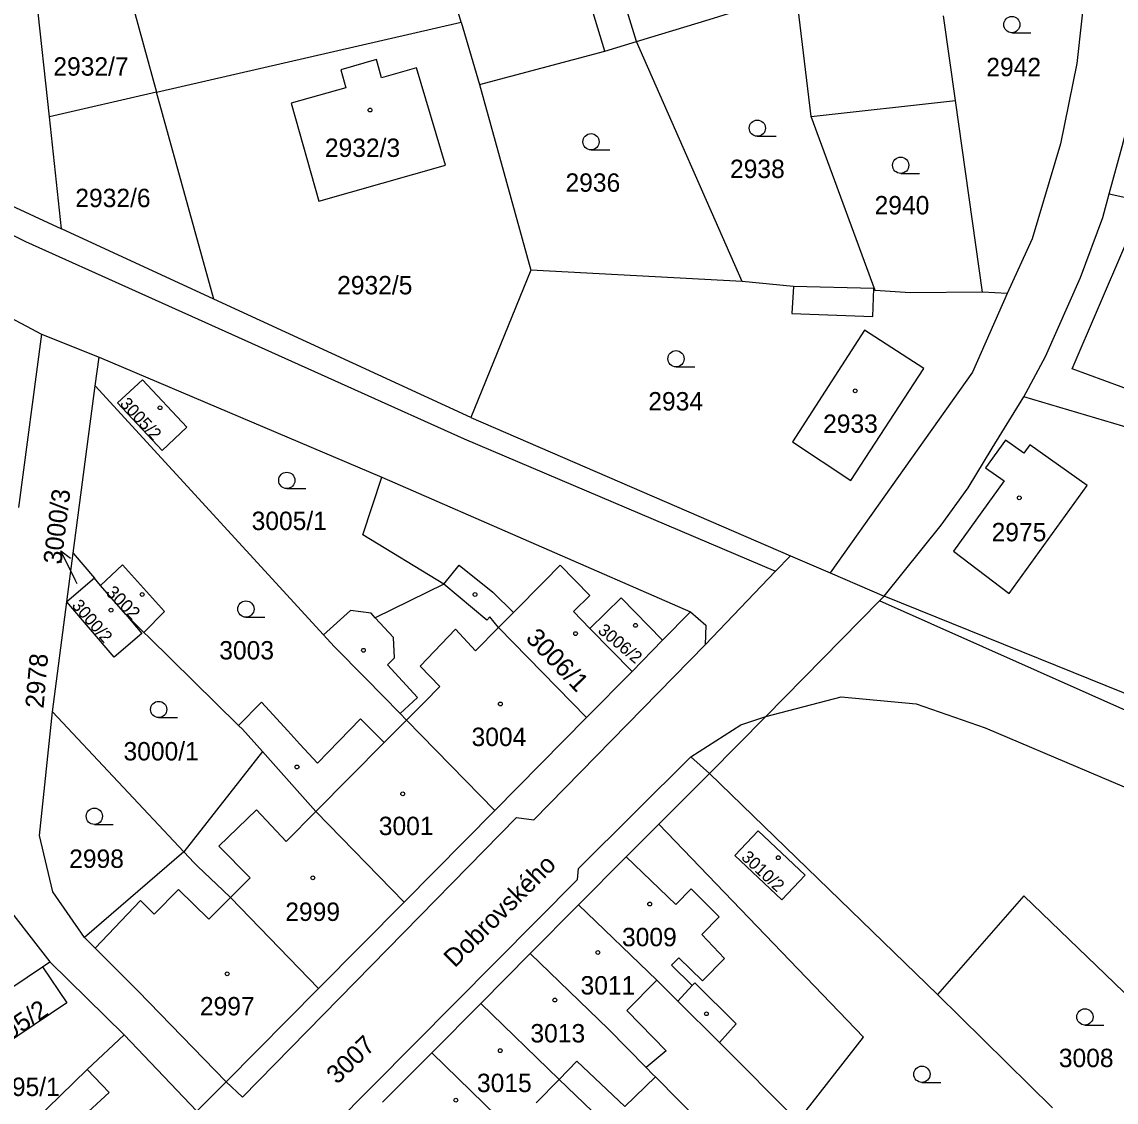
# Model space of a CAD drawing. Extents: x -527335 to -526256, y -1079142 to -1077836.
# Drawn here: x -526682.7 to -526581.6, y -1078714.2 to -1078614.4 of the extents above; entities that cross this region are included whole.
import ezdxf

# ---------------------------------------------------------------- set-up
doc = ezdxf.new("R2010")
doc.units = 0
for name, color, linetype in [('Hranice parcel', 7, 'Continuous'), ('Parcelní čísla', 7, 'Continuous'), ('Pop  PČ popisy', 7, 'Continuous'), ('Vnitřní kresba', 7, 'Continuous'), ('Značky budov', 7, 'Continuous'), ('Značky kultur', 7, 'Continuous')]:
    doc.layers.add(name, color=color, linetype=linetype)

msp = doc.modelspace()

# ---------------------------------------------------------------- linework, layer by layer
at = {"layer": 'Hranice parcel'}
for p, q in [((-526642.16, -1078614.41), (-526648.3, -1078593.48)), ((-526675.77, -1078601.05), (-526670.3, -1078620.85)), ((-526680.21, -1078623.13), (-526682.38, -1078602.87)), ((-526609.83, -1078623.11), (-526611.2, -1078611.62)), ((-526721.35, -1078614.01), (-526679.1, -1078633.49)), ((-526670.3, -1078620.85), (-526642.16, -1078614.41)), ((-526642.16, -1078614.41), (-526640.47, -1078620.16)), ((-526596.5, -1078621.62), (-526597.58, -1078613.8)), ((-526616.19, -1078638.37), (-526625.97, -1078616.19)), ((-526640.47, -1078620.16), (-526635.71, -1078637.32)), ((-526670.3, -1078620.85), (-526680.21, -1078623.13)), ((-526665.02, -1078639.98), (-526670.3, -1078620.85)), ((-526609.83, -1078623.11), (-526596.5, -1078621.62)), ((-526593.98, -1078639.34), (-526596.5, -1078621.62)), ((-526679.1, -1078633.49), (-526680.21, -1078623.13)), ((-526603.92, -1078639.18), (-526609.83, -1078623.11)), ((-526582.29, -1078630.26), (-526567.45, -1078633.62)), ((-526665.02, -1078639.98), (-526679.1, -1078633.49)), ((-526635.71, -1078637.32), (-526641.28, -1078650.93)), ((-526616.19, -1078638.37), (-526635.71, -1078637.32)), ((-526591.7, -1078639.47), (-526593.98, -1078639.34)), ((-526641.28, -1078650.93), (-526665.02, -1078639.98)), ((-526680.92, -1078643.22), (-526683.06, -1078659.24)), ((-526680.92, -1078643.22), (-526675.6, -1078645.35)), ((-526675.97, -1078647.99), (-526675.6, -1078645.35)), ((-526675.6, -1078645.35), (-526649.49, -1078656.45)), ((-526654.89, -1078671), (-526675.97, -1078647.99)), ((-526575.77, -1078653.31), (-526590.18, -1078649.02)), ((-526641.28, -1078650.93), (-526611.73, -1078663.7)), ((-526649.49, -1078656.45), (-526620.98, -1078668.88)), ((-526678.59, -1078667.96), (-526678, -1078663.47)), ((-526678, -1078663.47), (-526676.05, -1078665.78)), ((-526611.73, -1078663.7), (-526608.06, -1078665.29)), ((-526676.05, -1078665.78), (-526678.59, -1078667.96)), ((-526675.49, -1078666.45), (-526676.05, -1078665.78)), ((-526608.06, -1078665.29), (-526603.09, -1078667.44)), ((-526673.15, -1078669.14), (-526675.49, -1078666.45)), ((-526679.91, -1078678.13), (-526678.59, -1078667.96)), ((-526565.26, -1078682.7), (-526603.09, -1078667.44)), ((-526623.55, -1078671.51), (-526620.98, -1078668.88)), ((-526671.47, -1078670.79), (-526673.15, -1078669.14)), ((-526626.37, -1078674.41), (-526623.55, -1078671.51)), ((-526630.57, -1078678.66), (-526626.37, -1078674.41)), ((-526667.79, -1078691.06), (-526679.91, -1078678.13)), ((-526639.06, -1078687.24), (-526647.2, -1078678.89)), ((-526639.06, -1078687.24), (-526630.57, -1078678.66)), ((-526619.22, -1078683.84), (-526614.02, -1078678.55)), ((-526660.52, -1078681.79), (-526667.79, -1078691.06)), ((-526619.22, -1078683.84), (-526623.89, -1078688.51)), ((-526598.14, -1078704.26), (-526619.22, -1078683.84)), ((-526647.44, -1078695.71), (-526639.06, -1078687.24)), ((-526623.89, -1078688.51), (-526626.91, -1078691.53)), ((-526667.79, -1078691.06), (-526676.97, -1078698.98)), ((-526626.91, -1078691.53), (-526631.31, -1078695.96)), ((-526685.78, -1078694.02), (-526680.15, -1078701.23)), ((-526655.33, -1078703.7), (-526647.44, -1078695.71)), ((-526635.79, -1078700.47), (-526631.31, -1078695.96)), ((-526680.84, -1078701.69), (-526680.15, -1078701.23)), ((-526680.15, -1078701.23), (-526673.29, -1078707.97)), ((-526640.35, -1078705.07), (-526635.79, -1078700.47)), ((-526689.86, -1078707.76), (-526680.84, -1078701.69)), ((-526663.87, -1078712.33), (-526655.33, -1078703.7)), ((-526587.53, -1078714.71), (-526598.14, -1078704.26)), ((-526644.88, -1078709.64), (-526640.35, -1078705.07)), ((-526673.29, -1078707.97), (-526666.58, -1078715.02)), ((-526649.43, -1078714.21), (-526644.88, -1078709.64)), ((-526666.58, -1078715.02), (-526663.87, -1078712.33))]:
    msp.add_line(p, q, dxfattribs=at)
for points in [[(-526625.97, -1078616.19), (-526627.66, -1078610.64), (-526633.95, -1078589.47)], [(-526583.43, -1078599.56), (-526584.01, -1078606.72), (-526585.28, -1078618.21), (-526586.79, -1078625.64), (-526589.4, -1078634.43), (-526591.7, -1078639.47)], [(-526582.29, -1078630.26), (-526581.08, -1078625.88), (-526580.12, -1078622.23), (-526579.3, -1078618.4), (-526578.59, -1078614.59), (-526578.22, -1078610.5)], [(-526625.97, -1078616.19), (-526619.24, -1078614.14), (-526611.2, -1078611.62)], [(-526640.47, -1078620.16), (-526628.89, -1078617.08), (-526625.97, -1078616.19)], [(-526646.3, -1078618.62), (-526649.52, -1078619.53), (-526649.99, -1078617.86), (-526653.29, -1078618.79), (-526652.82, -1078620.46), (-526657.87, -1078621.89), (-526655.31, -1078630.94), (-526643.61, -1078627.6), (-526646.3, -1078618.62)], [(-526590.18, -1078649.02), (-526588.18, -1078645.3), (-526584.94, -1078638), (-526582.87, -1078632.45), (-526582.29, -1078630.26)], [(-526697.66, -1078634.2), (-526691.45, -1078637.64), (-526680.92, -1078643.22)], [(-526603.92, -1078639.18), (-526604.04, -1078639.02), (-526611.44, -1078638.83), (-526616.19, -1078638.37)], [(-526591.7, -1078639.47), (-526594.93, -1078646.75), (-526608.06, -1078665.29)], [(-526593.98, -1078639.34), (-526600.67, -1078639.4), (-526603.92, -1078639.18)], [(-526611.54, -1078653.18), (-526606.15, -1078656.74), (-526599.41, -1078646.41), (-526604.88, -1078642.86), (-526611.54, -1078653.18)], [(-526667.52, -1078651.81), (-526669.8, -1078653.97), (-526673.9, -1078649.58), (-526671.6, -1078647.44), (-526667.52, -1078651.81)], [(-526678, -1078663.47), (-526677.14, -1078656.92), (-526675.97, -1078647.99)], [(-526603.09, -1078667.44), (-526597.81, -1078660.87), (-526595.32, -1078657.42), (-526593.1, -1078653.76), (-526590.18, -1078649.02)], [(-526584.32, -1078657.2), (-526589.63, -1078653.45), (-526590.16, -1078654.21), (-526591.86, -1078653.02), (-526593.7, -1078655.57), (-526592, -1078656.79), (-526596.66, -1078663.28), (-526591.53, -1078667.19), (-526584.32, -1078657.2)], [(-526643.76, -1078666.34), (-526651.24, -1078661.76), (-526649.49, -1078656.45)], [(-526620.98, -1078668.88), (-526619.54, -1078670.11), (-526619.63, -1078671.93), (-526613.11, -1078665.14), (-526611.73, -1078663.7)], [(-526671.47, -1078670.79), (-526669.58, -1078668.85), (-526673.46, -1078664.53), (-526675.49, -1078666.45)], [(-526643.76, -1078666.34), (-526650.1, -1078669.43), (-526650.49, -1078669.01), (-526652.4, -1078668.75), (-526654.89, -1078671)], [(-526630.57, -1078678.66), (-526638.7, -1078670.33), (-526639.52, -1078669.35), (-526639.78, -1078669.66), (-526643.76, -1078666.34)], [(-526673.15, -1078669.14), (-526671.65, -1078670.9), (-526674.21, -1078673.09), (-526678.59, -1078667.96)], [(-526626.37, -1078674.41), (-526630.26, -1078670.43), (-526627.38, -1078667.6), (-526623.55, -1078671.51)], [(-526603.09, -1078667.44), (-526603.52, -1078667.88), (-526614.02, -1078678.55)], [(-526662.72, -1078679.38), (-526671.02, -1078671.23), (-526671.47, -1078670.79)], [(-526647.2, -1078678.89), (-526647.8, -1078678.29), (-526651.01, -1078675.02), (-526653.9, -1078672.08), (-526654.89, -1078671)], [(-526614.02, -1078678.55), (-526607.06, -1078676.75), (-526600.12, -1078677.39), (-526593.75, -1078679.6), (-526565.02, -1078691.82), (-526539.54, -1078702.51)], [(-526647.2, -1078678.89), (-526649.26, -1078680.97), (-526651.46, -1078678.78), (-526655.44, -1078682.86), (-526657.06, -1078681.11), (-526658.19, -1078679.88), (-526660.25, -1078677.64), (-526660.62, -1078677.24), (-526662.72, -1078679.38)], [(-526676.97, -1078698.98), (-526679.9, -1078694.76), (-526681.12, -1078689.56), (-526679.91, -1078678.13)], [(-526660.52, -1078681.79), (-526662.37, -1078679.72), (-526662.72, -1078679.38)], [(-526647.44, -1078695.71), (-526655.58, -1078687.34), (-526660.52, -1078681.79)], [(-526611.06, -1078715.96), (-526605, -1078708.2), (-526623.89, -1078688.51)], [(-526616.87, -1078691.41), (-526614.72, -1078689.13), (-526610.38, -1078693.21), (-526612.52, -1078695.5), (-526616.87, -1078691.41)], [(-526655.33, -1078703.7), (-526663.48, -1078695.3), (-526664.15, -1078694.63), (-526666.51, -1078692.39), (-526666.84, -1078692.07), (-526667.79, -1078691.06)], [(-526569.24, -1078715.32), (-526590.17, -1078695.14), (-526598.14, -1078704.26)], [(-526631.31, -1078695.96), (-526624.08, -1078702.91), (-526622.14, -1078704.85), (-526618.3, -1078708.7), (-526611.06, -1078715.96)], [(-526663.87, -1078712.33), (-526672.02, -1078703.91), (-526675.99, -1078699.96), (-526676.97, -1078698.98)], [(-526635.79, -1078700.47), (-526628.55, -1078707.46), (-526625.07, -1078711.01), (-526624.47, -1078711.62), (-526624.22, -1078711.87), (-526622.06, -1078714.05), (-526616.13, -1078720.06), (-526614.38, -1078721.84)], [(-526680.84, -1078701.69), (-526678.6, -1078705.01), (-526687.59, -1078711.07), (-526689.86, -1078707.76)], [(-526640.35, -1078705.07), (-526633.11, -1078712.1), (-526620.07, -1078724.6), (-526618.7, -1078726.19)], [(-526673.29, -1078707.97), (-526676.71, -1078711.19), (-526681.64, -1078715.99), (-526684.49, -1078719.05), (-526685.11, -1078719.62)], [(-526644.88, -1078709.64), (-526637.64, -1078716.69), (-526634.89, -1078719.43), (-526631.42, -1078722.73), (-526630.43, -1078723.74), (-526624.67, -1078729.64), (-526623.18, -1078731.02)]]:
    msp.add_lwpolyline(points, dxfattribs=at)
at = {"layer": 'Pop  PČ popisy'}
for p, q in [((-526679.15, -1078663.24), (-526679.16, -1078664.36)), ((-526677.83, -1078665.94), (-526679.15, -1078663.24)), ((-526679.15, -1078663.24), (-526678.26, -1078663.92)), ((-526677.65, -1078666.31), (-526677.83, -1078665.94))]:
    msp.add_line(p, q, dxfattribs=at)
at = {"layer": 'Vnitřní kresba'}
for p, q in [((-526628.89, -1078617.08), (-526630.58, -1078611.53)), ((-526720.61, -1078615.59), (-526682.42, -1078634.66)), ((-526682.42, -1078634.66), (-526641.87, -1078652.91)), ((-526585.7, -1078646.44), (-526580.83, -1078635.11)), ((-526611.44, -1078638.83), (-526611.61, -1078641.33)), ((-526604.11, -1078641.6), (-526604.04, -1078639.02)), ((-526611.61, -1078641.33), (-526604.11, -1078641.6)), ((-526579.66, -1078648.66), (-526585.7, -1078646.44)), ((-526641.87, -1078652.91), (-526613.11, -1078665.14)), ((-526643.76, -1078666.34), (-526642.36, -1078664.59)), ((-526642.36, -1078664.59), (-526639.23, -1078667.08)), ((-526633, -1078664.58), (-526634.5, -1078666.09)), ((-526630.26, -1078667.38), (-526633, -1078664.58)), ((-526637.34, -1078668.95), (-526634.5, -1078666.09)), ((-526639.23, -1078667.08), (-526637.34, -1078668.95)), ((-526631.78, -1078668.87), (-526630.26, -1078667.38)), ((-526563.25, -1078685.79), (-526603.52, -1078667.88)), ((-526637.34, -1078668.95), (-526638.7, -1078670.33)), ((-526631.78, -1078668.87), (-526630.26, -1078670.43)), ((-526645.96, -1078673.91), (-526642.68, -1078670.49)), ((-526642.68, -1078670.49), (-526640.85, -1078672.49)), ((-526640.85, -1078672.49), (-526638.7, -1078670.33)), ((-526635.45, -1078688.1), (-526619.63, -1078671.93)), ((-526644.12, -1078675.79), (-526645.96, -1078673.91)), ((-526645.56, -1078677.23), (-526644.12, -1078675.79)), ((-526647.2, -1078678.89), (-526645.56, -1078677.23)), ((-526616.33, -1078679.32), (-526614.02, -1078678.55)), ((-526620.93, -1078682.29), (-526616.33, -1078679.32)), ((-526649.26, -1078680.97), (-526655.58, -1078687.34)), ((-526631.32, -1078692.62), (-526620.93, -1078682.29)), ((-526620.93, -1078682.29), (-526619.22, -1078683.84)), ((-526664.54, -1078690.54), (-526661.08, -1078687.18)), ((-526661.08, -1078687.18), (-526658.32, -1078690.1)), ((-526662.36, -1078713.75), (-526637.04, -1078687.88)), ((-526658.32, -1078690.1), (-526655.58, -1078687.34)), ((-526637.04, -1078687.88), (-526635.45, -1078688.1)), ((-526661.67, -1078693.48), (-526664.54, -1078690.54)), ((-526626.91, -1078691.53), (-526622.33, -1078695.92)), ((-526631.42, -1078693.62), (-526631.32, -1078692.62)), ((-526663.48, -1078695.3), (-526661.67, -1078693.48)), ((-526659.29, -1078721.72), (-526631.42, -1078693.62)), ((-526670.53, -1078696.83), (-526668.27, -1078694.55)), ((-526668.27, -1078694.55), (-526665.46, -1078697.29)), ((-526665.46, -1078697.29), (-526663.48, -1078695.3)), ((-526622.33, -1078695.92), (-526620.9, -1078694.49)), ((-526620.9, -1078694.49), (-526618.33, -1078697.07)), ((-526675.99, -1078699.96), (-526671.78, -1078695.57)), ((-526671.78, -1078695.57), (-526670.53, -1078696.83)), ((-526618.33, -1078697.07), (-526619.92, -1078698.69)), ((-526619.92, -1078698.69), (-526617.83, -1078700.91)), ((-526622.05, -1078700.86), (-526622.72, -1078701.55)), ((-526619.87, -1078702.99), (-526622.05, -1078700.86)), ((-526617.83, -1078700.91), (-526619.87, -1078702.99)), ((-526622.72, -1078701.55), (-526620.81, -1078703.42)), ((-526624.08, -1078702.91), (-526626.85, -1078705.73)), ((-526620.81, -1078703.42), (-526620.58, -1078703.18)), ((-526620.58, -1078703.18), (-526616.74, -1078706.95)), ((-526620.81, -1078703.42), (-526622.14, -1078704.85)), ((-526626.85, -1078705.73), (-526623.23, -1078709.47)), ((-526616.74, -1078706.95), (-526618.3, -1078708.7)), ((-526633.11, -1078712.1), (-526631.46, -1078710.42)), ((-526623.23, -1078709.47), (-526625.07, -1078711.01)), ((-526674.67, -1078713.29), (-526676.71, -1078711.19)), ((-526663.87, -1078712.33), (-526662.36, -1078713.75)), ((-526635.23, -1078714.25), (-526633.11, -1078712.1)), ((-526679.72, -1078717.92), (-526674.67, -1078713.29))]:
    msp.add_line(p, q, dxfattribs=at)
for points in [[(-526647.8, -1078678.29), (-526646.18, -1078676.79), (-526648.96, -1078673.8), (-526648.31, -1078673.13), (-526648.41, -1078671.25), (-526650.1, -1078669.43)], [(-526624.22, -1078711.87), (-526627.03, -1078714.61), (-526631.46, -1078710.42)]]:
    msp.add_lwpolyline(points, dxfattribs=at)
at = {"layer": 'Značky budov'}
for centre in [(-526650.58, -1078622.52), (-526605.75, -1078648.47), (-526669.98, -1078650.03), (-526590.59, -1078658.35), (-526671.63, -1078667.29), (-526640.88, -1078667.28), (-526674.51, -1078668.73), (-526626.05, -1078670.14), (-526631.59, -1078670.9), (-526651.19, -1078672.44), (-526638.54, -1078677.4), (-526657.33, -1078683.22), (-526647.56, -1078685.71), (-526612.86, -1078691.61), (-526655.87, -1078693.47), (-526624.74, -1078695.89), (-526629.53, -1078700.37), (-526663.78, -1078702.34), (-526633.51, -1078704.76), (-526619.5, -1078706.03), (-526638.55, -1078709.44), (-526642.65, -1078714.01)]:
    msp.add_circle(centre, 0.175, dxfattribs=at)
at = {"layer": 'Značky kultur'}
for p, q in [((-526591.28, -1078615.37), (-526589.53, -1078615.37)), ((-526614.8, -1078624.94), (-526613.05, -1078624.94)), ((-526630.16, -1078626.2), (-526628.41, -1078626.2)), ((-526601.55, -1078628.37), (-526599.8, -1078628.37)), ((-526622.31, -1078646.25), (-526620.56, -1078646.25)), ((-526658.27, -1078657.49), (-526656.52, -1078657.49)), ((-526662.05, -1078669.38), (-526660.3, -1078669.38)), ((-526670.11, -1078678.66), (-526668.36, -1078678.66)), ((-526676.05, -1078688.53), (-526674.3, -1078688.53)), ((-526584.53, -1078707.07), (-526582.78, -1078707.07)), ((-526599.59, -1078712.37), (-526597.84, -1078712.37))]:
    msp.add_line(p, q, dxfattribs=at)
for centre in [(-526591.28, -1078614.62), (-526614.8, -1078624.19), (-526630.16, -1078625.45), (-526601.55, -1078627.62), (-526622.31, -1078645.5), (-526658.27, -1078656.74), (-526662.05, -1078668.63), (-526670.11, -1078677.91), (-526676.05, -1078687.78), (-526584.53, -1078706.32), (-526599.59, -1078711.62)]:
    msp.add_circle(centre, 0.75, dxfattribs=at)

# ---------------------------------------------------------------- texts
at = {"layer": 'Parcelní čísla'}
for s, p in [('2932/7', (-526679.84, -1078619.34)), ('2942', (-526593.64, -1078619.39)), ('2932/3', (-526654.75, -1078626.85)), ('2938', (-526617.32, -1078628.8)), ('2936', (-526632.52, -1078630.07)), ('2932/6', (-526677.81, -1078631.49)), ('2940', (-526603.96, -1078632.16)), ('2932/5', (-526653.62, -1078639.55)), ('2934', (-526624.87, -1078650.28)), ('2933', (-526608.72, -1078652.35)), ('3005/1', (-526661.52, -1078661.33)), ('2975', (-526593.15, -1078662.37)), ('3003', (-526664.51, -1078673.29)), ('3004', (-526641.2, -1078681.29)), ('3000/1', (-526673.36, -1078682.62)), ('3001', (-526649.77, -1078689.52)), ('2998', (-526678.38, -1078692.55)), ('2999', (-526658.41, -1078697.45)), ('3009', (-526627.3, -1078699.79)), ('3011', (-526631.13, -1078704.25)), ('2997', (-526666.3, -1078706.18)), ('3013', (-526635.76, -1078708.68)), ('3008', (-526586.94, -1078710.96)), ('2995/1', (-526686.2, -1078713.63)), ('3015', (-526640.7, -1078713.27))]:
    msp.add_text(s, height=1.7, dxfattribs=at).set_placement(p)
for s, height, rotation, p in [('3005/2', 1.14, 313, (-526673.76, -1078649.72)), ('3000/3', 1.7, 83, (-526679.1, -1078664.55)), ('3002', 1.2, 315, (-526675.07, -1078667.19)), ('3000/2', 1.14, 311, (-526678.2, -1078668.34)), ('3006/1', 1.7, 314, (-526636.28, -1078671.41)), ('3006/2', 1.139, 320, (-526629.61, -1078670.75)), ('2978', 1.7, 85, (-526680.75, -1078677.85)), ('3010/2', 1.14, 317, (-526616.36, -1078691.67)), ('2995/2', 1.7, 34, (-526685.92, -1078709.94)), ('3007', 1.7, 44, (-526653.62, -1078712.62))]:
    msp.add_text(s, height=height, rotation=rotation, dxfattribs=at).set_placement(p)
at = {"layer": 'Pop  PČ popisy'}
msp.add_text('Dobrovského', height=1.7, rotation=45, dxfattribs=at).set_placement((-526642.75, -1078701.85))

doc.saveas('drawing.dxf')
